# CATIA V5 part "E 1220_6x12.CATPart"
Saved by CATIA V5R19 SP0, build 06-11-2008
Definition: E 1220_6x12
Nomenclature: E 1220_6x12
Description: PART-E 1220_6x12_1-DESC
Material "Steel": density 7860 kg/m3, Young's modulus 2e+11 Pa, Poisson ratio 0.266, thermal expansion 1.17e-05 1/K
Bounding box of the stored display mesh (mm): x -29.772 to -15.628, y -18 to -6, z -21.717 to -9.366
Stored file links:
  G:\UTB\Kombinované\Bakalářská práce\Catia\FORMA\E 1220_6x12.CATPart
  D:\Aplikace\CATIA\Nová složka\win_b64\startup\materials\Catalog.CATMaterial
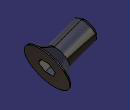
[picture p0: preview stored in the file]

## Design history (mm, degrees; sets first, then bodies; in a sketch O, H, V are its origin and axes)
Body1 "E 1220_6x12" (main body)
  Solid1: solid without history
